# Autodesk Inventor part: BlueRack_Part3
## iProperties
Shininess: 64.0
Length Units: 11272
Angle Units: 11279
Time Units: 11290
Mass Units: 11286
Length Display Precision: 3
Angle Display Precision: 2
Compacted: True
Part Number: BlueRack_Part3
Document SubType Name: Modeling
Created: 2004-12
Designer: John Blackburn
Manufacturer: Standard
Standards Organization: Custom
Material: Steel, Mild
Density: 0.0
Volumn: 0.0
Area: 0.0
PropertySet Name: Model Information
Control State: 0
Master: False
Checked Out: False
Author: John Blackburn
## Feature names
1. Extrusion1
2. Hole1
3. Rectangular Pattern1
